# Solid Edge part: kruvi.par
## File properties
Author: Mac
Template: Normal.par
Last saved by: Mac
Revision: 2
Application: Solid Edge
Material: ABS Plastic, medium impact
Face Style: Black
Fill Style: ANSI34(Plastic)
Virtual Style: Black (Shiny)
Coef. of Thermal Exp: 5.8e-05
Thermal Conductivity: 2.0
Specific Heat: 0.0
Modulus of Elasticity: 2275269810.0
Poission's Ratio: 0.4
Yield Stress: 43436969.1
Ultimate Stress: 0.0
Elongation: 0.0
Density: 1024,000 kg/m^3
Accuracy: 0,990
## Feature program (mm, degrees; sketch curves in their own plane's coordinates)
sketch for "unnamed RevolvedProtrusion 1" plane through (0, 0, 0) normal (0, 0, 1) x-axis (1, 0, 0)
  line (0, 0.6) -> (0.2, 0.6)
  bspline degree 3 poles (0, 0) (0.1177, 0.0505) (0.199, 0.245) (0.2, 0.6) knots 0 1 multiplicities 4 4
revolve "unnamed RevolvedProtrusion 1" add finite 360 deg about sketch line (0, 0.6) -> (0, 0)
lofted protrusion "unnamed LoftedProtrusion 1"
pattern "unnamed Pattern 1" of "unnamed LoftedProtrusion 1"
lofted protrusion "unnamed LoftedProtrusion 2"
lofted protrusion "unnamed LoftedProtrusion 3"
sketch for "unnamed Cutout 1" plane through (0, 0.6, 0) normal (0, 1, 0) x-axis (-1, 0, 0)
  circle centre (0, 0) radius 0.0514
extrude "unnamed Cutout 1" cut finite 0.459 along -normal
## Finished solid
Body 1: solid body, 19 faces, 39 edges, 24 vertices.
  Faces by surface: spline 12, plane 5, cylinder 1, spun 1
  Edges by curve: intersection 12, spline 12, circle 9, curve on surface 6
Bounding box of the edges (mm; curved faces can reach further): 3.606 x 0.632 x 3.570, from (-1.7778, 0.0097, -1.6226) to (1.8286, 0.6419, 1.9472).
Cylindrical faces by radius (mm): R0.0514 x1
Planar faces by outward normal: +y 2, +z 1, oblique 2
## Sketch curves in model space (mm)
arc centre (0.1761, 0.3986, 1.9472) radius 0.0068 from (0.1758, 0.4054, 1.9472) through (0.1828, 0.3992, 1.9472) to (0.1774, 0.392, 1.9472)
spline (-0.2291, 0.2562, 1.9472) -> (-0.0485, 0.3443, 1.9472) -> (0.1774, 0.392, 1.9472)
arc centre (-0.2322, 0.2604, 1.9472) radius 0.0051 from (-0.2362, 0.2636, 1.9472) through (-0.2359, 0.2568, 1.9472) to (-0.2291, 0.2562, 1.9472)
spline (-0.2362, 0.2636, 1.9472) -> (-0.0844, 0.3467, 1.9472) -> (0.1758, 0.4054, 1.9472)
arc centre (0.7669, 0.5626, 1.4827) radius 0.0165 from (0.7675, 0.5791, 1.4827) through (0.7834, 0.5627, 1.4827) to (0.7677, 0.5461, 1.4827)
spline (0.7677, 0.5461, 1.4827) -> (-0.2807, 0.3909, 1.4827) -> (-0.9839, 0.0319, 1.4827)
arc centre (-0.9932, 0.0374, 1.4827) radius 0.0108 from (-1.0035, 0.0407, 1.4827) through (-0.997, 0.0273, 1.4827) to (-0.9839, 0.0319, 1.4827)
spline (-1.0035, 0.0407, 1.4827) -> (-0.1664, 0.4894, 1.4827) -> (0.7675, 0.5791, 1.4827)
arc centre (0.1048, 0.5681, 0) radius 0.0109 from (0.1071, 0.5575, 0) through (0.1157, 0.5687, 0) to (0.1071, 0.5787, 0)
spline (-0.0792, 0.4573, 0) -> (-0.0055, 0.5212, 0) -> (0.1071, 0.5575, 0)
arc centre (-0.0817, 0.4581, 0) radius 0.0026 from (-0.0841, 0.459, 0) through (-0.0826, 0.4556, 0) to (-0.0792, 0.4573, 0)
spline (-0.0841, 0.459, 0) -> (-0.0219, 0.5301, 0) -> (0.1071, 0.5787, 0)
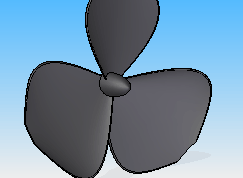
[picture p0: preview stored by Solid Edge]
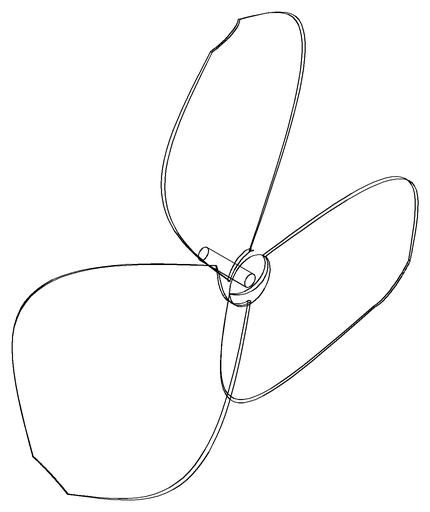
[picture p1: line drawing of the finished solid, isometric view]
